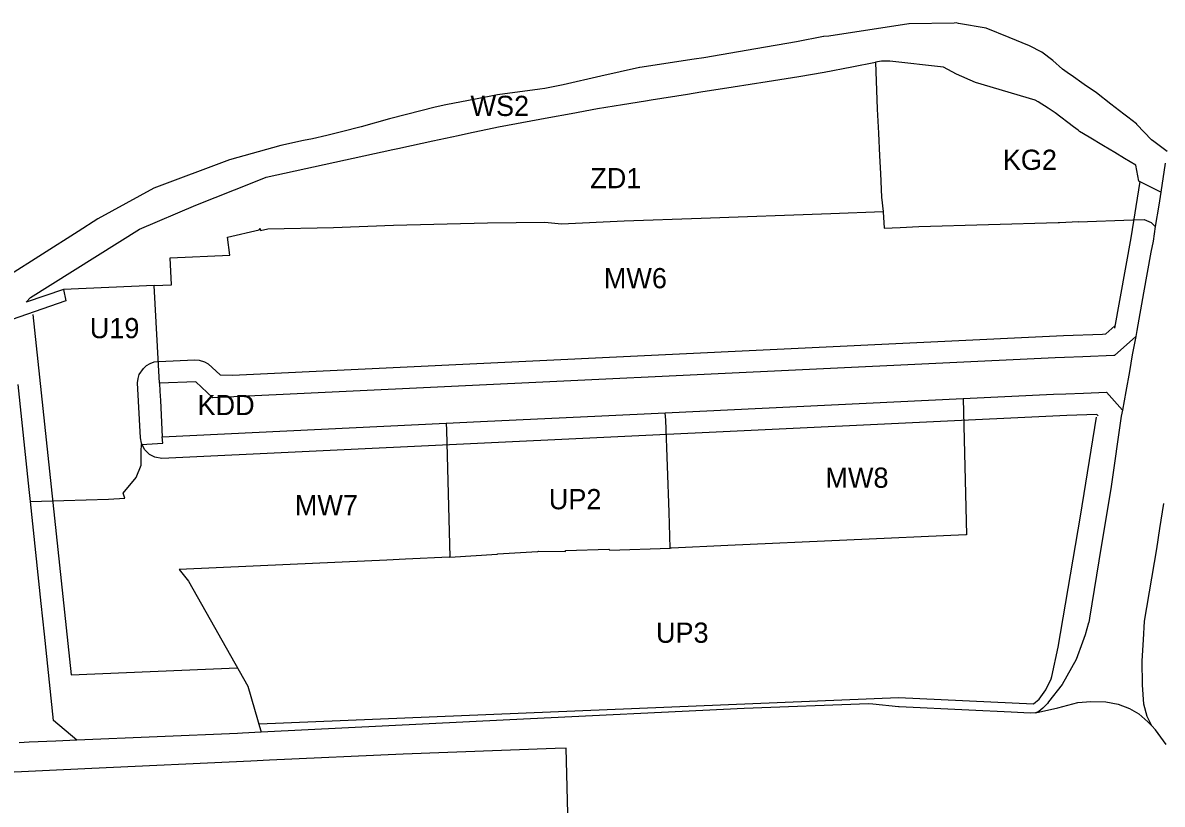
# Model space of a CAD drawing. Extents: x 7428080 to 7432143, y 5545880 to 5549217.
# Drawn here: x 7428821 to 7429133.6, y 5547975.6 to 5548190.1 of the extents above; entities that cross this region are included whole.
import ezdxf

# ---------------------------------------------------------------- set-up
doc = ezdxf.new("R2010")
doc.units = 0
for name, color, linetype in [('CZ_L_linie rozgraniczające tereny o różnym przeznaczeniu oraz różnych warunkach ich zabudowy i zagospodarowania', 7, 'Continuous'), ('CZ_L_maksymalne nieprzekraczalne linie zabudowy', 7, 'Continuous'), ('CZ_L_opisy_linie rozgraniczające tereny o różnym przeznaczeniu oraz różnych warunkach ich zabudowy i zagospodarowania', 7, 'Continuous'), ('info', 7, 'Continuous')]:
    doc.layers.add(name, color=color, linetype=linetype)

msp = doc.modelspace()

# ---------------------------------------------------------------- linework, layer by layer
at = {"layer": 'CZ_L_linie rozgraniczające tereny o różnym przeznaczeniu oraz różnych warunkach ich zabudowy i zagospodarowania'}
for p, q in [((7429064.11, 5548189.78), (7429042.15, 5548186.37)), ((7429064.18, 5548189.79), (7429064.11, 5548189.78)), ((7429076.51, 5548189.95), (7429064.18, 5548189.79)), ((7429077.09, 5548190.07), (7429076.51, 5548189.95)), ((7429077.7, 5548189.87), (7429077.09, 5548190.07)), ((7429085.25, 5548188.56), (7429077.7, 5548189.87)), ((7429040.67, 5548186.3), (7429033.24, 5548184.85)), ((7429040.8, 5548186.34), (7429040.67, 5548186.3)), ((7429042.15, 5548186.37), (7429040.8, 5548186.34)), ((7429091.62, 5548186.03), (7429085.25, 5548188.56)), ((7429097.17, 5548183.73), (7429091.62, 5548186.03)), ((7429022.14, 5548182.9), (7429007.81, 5548180.46)), ((7429033.24, 5548184.85), (7429022.14, 5548182.9)), ((7429100.61, 5548181.97), (7429097.17, 5548183.73)), ((7429005.16, 5548180.06), (7428990.24, 5548177.83)), ((7429007.81, 5548180.46), (7429005.16, 5548180.06)), ((7429103.59, 5548179.69), (7429100.61, 5548181.97)), ((7428990.15, 5548177.81), (7428979.61, 5548175.41)), ((7428990.24, 5548177.83), (7428990.15, 5548177.81)), ((7429040.85, 5548176.51), (7429048.41, 5548178)), ((7429048.41, 5548178), (7429054.91, 5548179.25)), ((7429056.55, 5548179.56), (7429054.91, 5548179.25)), ((7429054.91, 5548179.25), (7429055.41, 5548166.32)), ((7429058.83, 5548179.5), (7429056.55, 5548179.56)), ((7429073.57, 5548177.92), (7429058.83, 5548179.5)), ((7429077.13, 5548175.98), (7429073.57, 5548177.92)), ((7429106.26, 5548177.3), (7429103.59, 5548179.69)), ((7429108.17, 5548175.94), (7429106.26, 5548177.3)), ((7428979.61, 5548175.41), (7428969.25, 5548173)), ((7429015.86, 5548172.49), (7429025.23, 5548173.99)), ((7429025.23, 5548173.99), (7429033.88, 5548175.36)), ((7429033.88, 5548175.36), (7429040.85, 5548176.51)), ((7429082.38, 5548173.64), (7429077.13, 5548175.98)), ((7429098.74, 5548168.83), (7429082.38, 5548173.64)), ((7429108.18, 5548175.96), (7429108.17, 5548175.94)), ((7429108.64, 5548175.65), (7429108.18, 5548175.96)), ((7429112.21, 5548173.16), (7429108.64, 5548175.65)), ((7428962.81, 5548171.82), (7428951.22, 5548170.29)), ((7428964.18, 5548172.07), (7428962.81, 5548171.82)), ((7428969.25, 5548173), (7428964.18, 5548172.07)), ((7428993.43, 5548168.89), (7429003.34, 5548170.49)), ((7429003.34, 5548170.49), (7429007.05, 5548171.09)), ((7429007.05, 5548171.09), (7429015.86, 5548172.49)), ((7429115.56, 5548170.83), (7429112.21, 5548173.16)), ((7429119.54, 5548167.75), (7429115.56, 5548170.83)), ((7428937.04, 5548167.59), (7428934.13, 5548166.87)), ((7428945.18, 5548169.12), (7428937.04, 5548167.59)), ((7428951.22, 5548170.29), (7428945.18, 5548169.12)), ((7428978.66, 5548166.51), (7428985.53, 5548167.62)), ((7428985.53, 5548167.62), (7428991.87, 5548168.64)), ((7428991.87, 5548168.64), (7428993.43, 5548168.89)), ((7429099.53, 5548168.33), (7429098.74, 5548168.83)), ((7429102.28, 5548166.6), (7429099.53, 5548168.33)), ((7429123.1, 5548164.99), (7429119.54, 5548167.75)), ((7428926.29, 5548164.91), (7428921.57, 5548163.66)), ((7428934.13, 5548166.87), (7428926.29, 5548164.91)), ((7428965.34, 5548164.08), (7428971.45, 5548165.2)), ((7428971.45, 5548165.2), (7428978.66, 5548166.51)), ((7429055.41, 5548166.32), (7429055.71, 5548159.79)), ((7429104.25, 5548165.35), (7429102.28, 5548166.6)), ((7429109.25, 5548161.51), (7429104.25, 5548165.35)), ((7429124.13, 5548164.18), (7429123.1, 5548164.99)), ((7429126.54, 5548162.3), (7429124.13, 5548164.18)), ((7428913.85, 5548161.49), (7428908.42, 5548160.13)), ((7428921.57, 5548163.66), (7428913.85, 5548161.49)), ((7428943.25, 5548159.74), (7428951.47, 5548161.55)), ((7428951.47, 5548161.55), (7428962.83, 5548163.62)), ((7428962.83, 5548163.62), (7428965.34, 5548164.08)), ((7429110.5, 5548160.56), (7429109.25, 5548161.51)), ((7429126.64, 5548162.23), (7429126.54, 5548162.3)), ((7429126.67, 5548162.16), (7429126.64, 5548162.23)), ((7429130.69, 5548157.9), (7429126.67, 5548162.16)), ((7428900.44, 5548158.19), (7428897.97, 5548157.76)), ((7428904.41, 5548159.12), (7428900.44, 5548158.19)), ((7428908.42, 5548160.13), (7428904.41, 5548159.12)), ((7428933.5, 5548157.64), (7428940.48, 5548159.13)), ((7428940.48, 5548159.13), (7428943.25, 5548159.74)), ((7429055.71, 5548159.79), (7429056.03, 5548153.57)), ((7429110.93, 5548160.25), (7429110.5, 5548160.56)), ((7429113.51, 5548158.7), (7429110.93, 5548160.25)), ((7429117.49, 5548156.31), (7429113.51, 5548158.7)), ((7429131.28, 5548157.46), (7429130.69, 5548157.9)), ((7428891.76, 5548156.42), (7428877.66, 5548152.43)), ((7428887.78, 5548147.7), (7428922.5, 5548155.31)), ((7428897.97, 5548157.76), (7428891.76, 5548156.42)), ((7428922.5, 5548155.31), (7428923.92, 5548155.54)), ((7428923.92, 5548155.54), (7428927.6, 5548156.39)), ((7428927.6, 5548156.39), (7428933.5, 5548157.64)), ((7429120.63, 5548154.42), (7429117.49, 5548156.31)), ((7429134.92, 5548154.74), (7429131.28, 5548157.46)), ((7428877.66, 5548152.43), (7428856.96, 5548144.68)), ((7429056.03, 5548153.57), (7429056.28, 5548148.72)), ((7429123.25, 5548152.85), (7429120.63, 5548154.42)), ((7429124.77, 5548151.94), (7429123.25, 5548152.85)), ((7429126.36, 5548150.99), (7429124.77, 5548151.94)), ((7429056.28, 5548148.72), (7429056.55, 5548142.19)), ((7429127.17, 5548146.62), (7429126.36, 5548150.99)), ((7429134.43, 5548151.49), (7429133.18, 5548143.55)), ((7428868.49, 5548140.04), (7428884.34, 5548146.34)), ((7428884.34, 5548146.34), (7428887.78, 5548147.7)), ((7429133.18, 5548143.55), (7429127.17, 5548146.62)), ((7428856.96, 5548144.68), (7428841.54, 5548136.21)), ((7429133.18, 5548143.55), (7429132.62, 5548140.01)), ((7428853.01, 5548133.41), (7428868.49, 5548140.04)), ((7429056.55, 5548142.19), (7429057.05, 5548138.28)), ((7429132.62, 5548140.01), (7429131.7, 5548134.17)), ((7428841.54, 5548136.21), (7428836.16, 5548132.82)), ((7428985.97, 5548135.71), (7429007.13, 5548136.46)), ((7429007.13, 5548136.46), (7429042.7, 5548137.74)), ((7429042.7, 5548137.74), (7429057.05, 5548138.28)), ((7429057.05, 5548138.28), (7429057.06, 5548138.16)), ((7429057.06, 5548138.16), (7429057.3, 5548133.66)), ((7429110.64, 5548135.44), (7429125.49, 5548135.97)), ((7429125.49, 5548135.97), (7429128.68, 5548136.08)), ((7429128.68, 5548136.08), (7429130.6, 5548135.27)), ((7428823.07, 5548114.63), (7428853.01, 5548133.41)), ((7428877.12, 5548131.24), (7428885.8, 5548133.21)), ((7428885.8, 5548133.21), (7428886.1, 5548133.59)), ((7428886.1, 5548133.59), (7428886.17, 5548133.08)), ((7428886.17, 5548133.08), (7428888.26, 5548133.51)), ((7428888.26, 5548133.51), (7428906.22, 5548133.84)), ((7428906.22, 5548133.84), (7428922.68, 5548134.51)), ((7428922.68, 5548134.51), (7428948.46, 5548135.15)), ((7428948.46, 5548135.15), (7428964.2, 5548135.31)), ((7428964.2, 5548135.31), (7428968.81, 5548134.9)), ((7428968.81, 5548134.9), (7428985.97, 5548135.71)), ((7429057.3, 5548133.66), (7429061.69, 5548133.9)), ((7429061.69, 5548133.9), (7429066.85, 5548134.19)), ((7429066.85, 5548134.19), (7429105.03, 5548135.24)), ((7429105.03, 5548135.24), (7429105.45, 5548135.25)), ((7429105.45, 5548135.25), (7429110.63, 5548135.49)), ((7429110.63, 5548135.49), (7429110.64, 5548135.44)), ((7429130.6, 5548135.27), (7429131.7, 5548134.17)), ((7429131.7, 5548134.17), (7429131.07, 5548130.13)), ((7428836.16, 5548132.82), (7428816.6, 5548120.32)), ((7428877.75, 5548126.29), (7428877.12, 5548131.24)), ((7429131.07, 5548130.13), (7429130.49, 5548127.14)), ((7429130.49, 5548127.14), (7429128.48, 5548115.99)), ((7428861.46, 5548125.52), (7428877.75, 5548126.29)), ((7428861.76, 5548118.17), (7428861.46, 5548125.52)), ((7428857.01, 5548117.96), (7428832.19, 5548116.86)), ((7428857.01, 5548117.96), (7428861.76, 5548118.17)), ((7428858.47, 5548091.14), (7428857.01, 5548117.96)), ((7428832.19, 5548116.86), (7428821.96, 5548113.38)), ((7428821.96, 5548113.38), (7428823.07, 5548114.63)), ((7428832.19, 5548116.86), (7428832.77, 5548113.71)), ((7429128.48, 5548115.99), (7429126.6, 5548105.63)), ((7428832.77, 5548113.71), (7428817.83, 5548108.57)), ((7429126.6, 5548105.63), (7429126.31, 5548104)), ((7429126.31, 5548104), (7429120.47, 5548098.74)), ((7429126.31, 5548104), (7429125.39, 5548098.95)), ((7429120.31, 5548098.73), (7429111.79, 5548098.42)), ((7429120.47, 5548098.74), (7429120.31, 5548098.73)), ((7429125.39, 5548098.95), (7429124.58, 5548094.32)), ((7429104.24, 5548098.12), (7428873.14, 5548087.12)), ((7429106.81, 5548098.24), (7429104.24, 5548098.12)), ((7429111.79, 5548098.42), (7429106.81, 5548098.24)), ((7429124.58, 5548094.32), (7429123.6, 5548088.87)), ((7428822.74, 5548061.99), (7428819.71, 5548090.75)), ((7428868.43, 5548091.55), (7428858.47, 5548091.14)), ((7428858.47, 5548091.14), (7428858.59, 5548088.94)), ((7428873.14, 5548087.12), (7428868.43, 5548091.55)), ((7428858.59, 5548088.94), (7428858.73, 5548086.43)), ((7428858.73, 5548086.43), (7428859.27, 5548076.45)), ((7428997.26, 5548083.02), (7429079.02, 5548086.91)), ((7429079.02, 5548086.91), (7429103.79, 5548088.09)), ((7429079.02, 5548086.91), (7429079.94, 5548049.51)), ((7429103.79, 5548088.09), (7429107.15, 5548088.25)), ((7429107.15, 5548088.25), (7429112.04, 5548088.43)), ((7429112.04, 5548088.43), (7429118.3, 5548088.67)), ((7429118.3, 5548088.67), (7429122.67, 5548083.72)), ((7429123.6, 5548088.87), (7429122.67, 5548083.72)), ((7428979.81, 5548082.19), (7428997.26, 5548083.02)), ((7428997.26, 5548083.01), (7428997.26, 5548083.02)), ((7428997.26, 5548083), (7428997.26, 5548083.01)), ((7428997.41, 5548081.04), (7428997.26, 5548083)), ((7429122.67, 5548083.72), (7429122.37, 5548082.09)), ((7428859.27, 5548076.45), (7428937.17, 5548080.15)), ((7428937.17, 5548080.15), (7428946.53, 5548080.6)), ((7428937.17, 5548080.15), (7428937.25, 5548078.25)), ((7428946.53, 5548080.6), (7428979.81, 5548082.19)), ((7428998.32, 5548055.72), (7428997.41, 5548081.04)), ((7429122.37, 5548082.09), (7429119.6, 5548062.76)), ((7428937.25, 5548078.25), (7428938.14, 5548043.39)), ((7428853.51, 5548072.52), (7428853.54, 5548074.35)), ((7428853.54, 5548074.35), (7428859.37, 5548074.64)), ((7428859.37, 5548074.64), (7428859.27, 5548076.45)), ((7428853.45, 5548068.65), (7428853.47, 5548070.36)), ((7428853.47, 5548070.36), (7428853.51, 5548072.52)), ((7428852.08, 5548065.27), (7428853.45, 5548068.65)), ((7428850.28, 5548063.05), (7428851.24, 5548064.23)), ((7428851.24, 5548064.23), (7428852.08, 5548065.27)), ((7428823.09, 5548058.69), (7428822.74, 5548061.99)), ((7428848.55, 5548060.93), (7428850.28, 5548063.05)), ((7429119.6, 5548062.76), (7429116.25, 5548042.34)), ((7428823.09, 5548058.69), (7428826.11, 5548058.79)), ((7428826.05, 5548030.63), (7428823.09, 5548058.69)), ((7428826.11, 5548058.79), (7428844.47, 5548059.32)), ((7428844.47, 5548059.32), (7428849.02, 5548059.58)), ((7428849.02, 5548059.58), (7428848.55, 5548060.93)), ((7429132.96, 5548051.26), (7429134.01, 5548058.16)), ((7428998.64, 5548045.84), (7428998.32, 5548055.72)), ((7429079.69, 5548049.5), (7429014.43, 5548046.56)), ((7429079.94, 5548049.51), (7429079.69, 5548049.5)), ((7429132.12, 5548045.7), (7429132.96, 5548051.26)), ((7428970, 5548045.18), (7428981.75, 5548045.6)), ((7428981.75, 5548045.6), (7428982.05, 5548045.3)), ((7428982.05, 5548045.3), (7428998.64, 5548045.84)), ((7428998.68, 5548045.85), (7428998.64, 5548045.84)), ((7428998.97, 5548045.85), (7428998.68, 5548045.85)), ((7429014.43, 5548046.56), (7428998.97, 5548045.85)), ((7429128.73, 5548025.84), (7429132.12, 5548045.7)), ((7428920.86, 5548042.61), (7428894.33, 5548041.38)), ((7428925.96, 5548042.84), (7428920.86, 5548042.61)), ((7428938.01, 5548043.4), (7428925.96, 5548042.84)), ((7428938.04, 5548043.38), (7428938.01, 5548043.4)), ((7428938.14, 5548043.39), (7428938.04, 5548043.38)), ((7428938.14, 5548043.39), (7428951.11, 5548044.18)), ((7428951.11, 5548044.18), (7428951.32, 5548044.3)), ((7428951.32, 5548044.3), (7428962.23, 5548044.96)), ((7428962.23, 5548044.96), (7428962.26, 5548044.93)), ((7428962.26, 5548044.93), (7428962.53, 5548045.04)), ((7428962.53, 5548045.04), (7428969.79, 5548044.95)), ((7428969.79, 5548044.95), (7428970, 5548045.18)), ((7429116.25, 5548042.34), (7429113.62, 5548026.67)), ((7428894.33, 5548041.38), (7428863.85, 5548039.97)), ((7428863.85, 5548039.97), (7428866.47, 5548036.85)), ((7428866.47, 5548036.85), (7428882.69, 5548007.94)), ((7428826.93, 5548022.22), (7428826.05, 5548030.63)), ((7429113.62, 5548026.67), (7429113.42, 5548025.46)), ((7429113.41, 5548025.36), (7429112.5, 5548022.06)), ((7429113.42, 5548025.46), (7429113.41, 5548025.36)), ((7429128.49, 5548020.7), (7429128.73, 5548025.84)), ((7428829.43, 5547998.56), (7428826.93, 5548022.22)), ((7429112.5, 5548022.06), (7429111.75, 5548020.04)), ((7429128.13, 5548014.98), (7429128.49, 5548020.7)), ((7429111.75, 5548020.04), (7429109.95, 5548015.27)), ((7429109.95, 5548015.27), (7429106.12, 5548008.44)), ((7429128.14, 5548008.39), (7429128.13, 5548014.98)), ((7428882.69, 5548007.94), (7428886.43, 5547995.35)), ((7429106.12, 5548008.44), (7429102.43, 5548003.66)), ((7429128.53, 5548003), (7429128.14, 5548008.39)), ((7429018.88, 5548001.85), (7428954.57, 5547998.7)), ((7429053, 5548003.17), (7429018.88, 5548001.85)), ((7429054.24, 5548003.06), (7429053, 5548003.17)), ((7429061.25, 5548002.35), (7429054.24, 5548003.06)), ((7429061.39, 5548002.33), (7429061.25, 5548002.35)), ((7429080.58, 5548001.4), (7429061.39, 5548002.33)), ((7429098.83, 5548000.62), (7429104.94, 5548002.05)), ((7429100.8, 5548001.94), (7429099.72, 5548001.03)), ((7429102.09, 5548003.21), (7429100.8, 5548001.94)), ((7429102.43, 5548003.66), (7429102.09, 5548003.21)), ((7429104.94, 5548002.05), (7429110.45, 5548003.54)), ((7429110.45, 5548003.54), (7429114.02, 5548003.75)), ((7429114.02, 5548003.75), (7429118.08, 5548003.67)), ((7429118.08, 5548003.67), (7429121.5, 5548003.02)), ((7429121.5, 5548003.02), (7429124.64, 5548001.89)), ((7429124.64, 5548001.89), (7429127.18, 5548000.41)), ((7429129.43, 5547999.7), (7429128.53, 5548003)), ((7428835.81, 5547993.13), (7428829.43, 5547998.56)), ((7428954.57, 5547998.7), (7428886.43, 5547995.35)), ((7429092.15, 5548000.84), (7429080.58, 5548001.4)), ((7429097.35, 5548000.59), (7429092.15, 5548000.84)), ((7429098.83, 5548000.62), (7429097.35, 5548000.59)), ((7429099.72, 5548001.03), (7429098.83, 5548000.62)), ((7429127.18, 5548000.41), (7429129.63, 5547998.2)), ((7429130.7, 5547997.11), (7429129.43, 5547999.7)), ((7428886.43, 5547995.35), (7428881.28, 5547995.09)), ((7429129.63, 5547998.2), (7429130.7, 5547997.11)), ((7429131.78, 5547996.01), (7429130.7, 5547997.11)), ((7429134.67, 5547991.98), (7429131.78, 5547996.01)), ((7428822.71, 5547992.57), (7428820.02, 5547992.45)), ((7428830.02, 5547992.88), (7428822.71, 5547992.57)), ((7428835.81, 5547993.13), (7428830.02, 5547992.88)), ((7428879.94, 5547995.03), (7428835.81, 5547993.13)), ((7428881.28, 5547995.09), (7428879.94, 5547995.03))]:
    msp.add_line(p, q, dxfattribs=at)
at = {"layer": 'CZ_L_maksymalne nieprzekraczalne linie zabudowy'}
for points in [[(7429120.62, 5548106.26), (7429125.12, 5548131), (7429127.57, 5548146.53)], [(7428823.72, 5548109.97), (7428834.23, 5548011.08), (7428879.79, 5548013.04)], [(7429116.02, 5548082.19), (7429115.69, 5548082.56), (7429107.39, 5548082.25), (7428859.13, 5548070.45), (7428857.25, 5548070.8), (7428855.79, 5548071.56), (7428854.41, 5548072.93), (7428853.54, 5548074.67), (7428853.28, 5548076.1), (7428852.47, 5548091.28), (7428852.62, 5548092.46), (7428852.96, 5548093.52), (7428854.07, 5548095.22), (7428854.92, 5548095.98), (7428855.95, 5548096.58), (7428857.07, 5548096.97), (7428858.21, 5548097.13), (7428868.2, 5548097.54), (7428869.39, 5548097.47), (7428870.86, 5548097.03), (7428871.89, 5548096.45), (7428875.15, 5548093.46), (7428878.48, 5548093.38), (7429106.54, 5548104.23), (7429117.2, 5548104.62), (7429118.12, 5548104.7), (7429120.59, 5548106.93)], [(7428885.88, 5547997.64), (7429061.21, 5548004.84), (7429098.31, 5548003.1), (7429099.83, 5548004.39), (7429101.68, 5548006.97), (7429103.14, 5548010), (7429103.3, 5548010.66), (7429105.04, 5548018.72), (7429111.13, 5548054.61), (7429115.58, 5548081.83)]]:
    msp.add_lwpolyline(points, dxfattribs=at)
at = {"layer": 'info'}
msp.add_lwpolyline([(7428970.64, 5547969.46), (7428970.03, 5547991.01), (7428967.02, 5547990.9), (7428925.33, 5547989.29), (7428888.69, 5547987.65), (7428883.55, 5547987.41), (7428839.9, 5547985.35), (7428799.26, 5547983.42)], dxfattribs=at)

# ---------------------------------------------------------------- texts
at = {"layer": 'CZ_L_opisy_linie rozgraniczające tereny o różnym przeznaczeniu oraz różnych warunkach ich zabudowy i zagospodarowania'}
for s, p in [('WS2', (7428943.82, 5548164.48)), ('KG2', (7429089.86, 5548149.69)), ('ZD1', (7428976.67, 5548144.66)), ('MW6', (7428980.4, 5548117.2)), ('U19', (7428839.37, 5548103.49)), ('KDD', (7428868.93, 5548082.38)), ('MW8', (7429041.19, 5548062.43)), ('UP2', (7428965.31, 5548056.54)), ('MW7', (7428895.63, 5548054.88)), ('UP3', (7428994.7, 5548019.89))]:
    msp.add_text(s, height=5.549, dxfattribs=at).set_placement(p)

doc.saveas('drawing.dxf')
